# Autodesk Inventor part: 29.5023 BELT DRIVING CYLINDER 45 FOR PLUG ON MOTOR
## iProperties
Created: 2007-04
Part Number: 29.5023 BELT DRIVING CYLINDER 45 FOR PLUG ON MOTOR
Document SubType Name: Modeling
Designer: Andy Moles
Material: Steel
Density: 7.85 g/cm^3
Author: Andy Moles
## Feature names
1. Revolution2
2. Extrusion2
